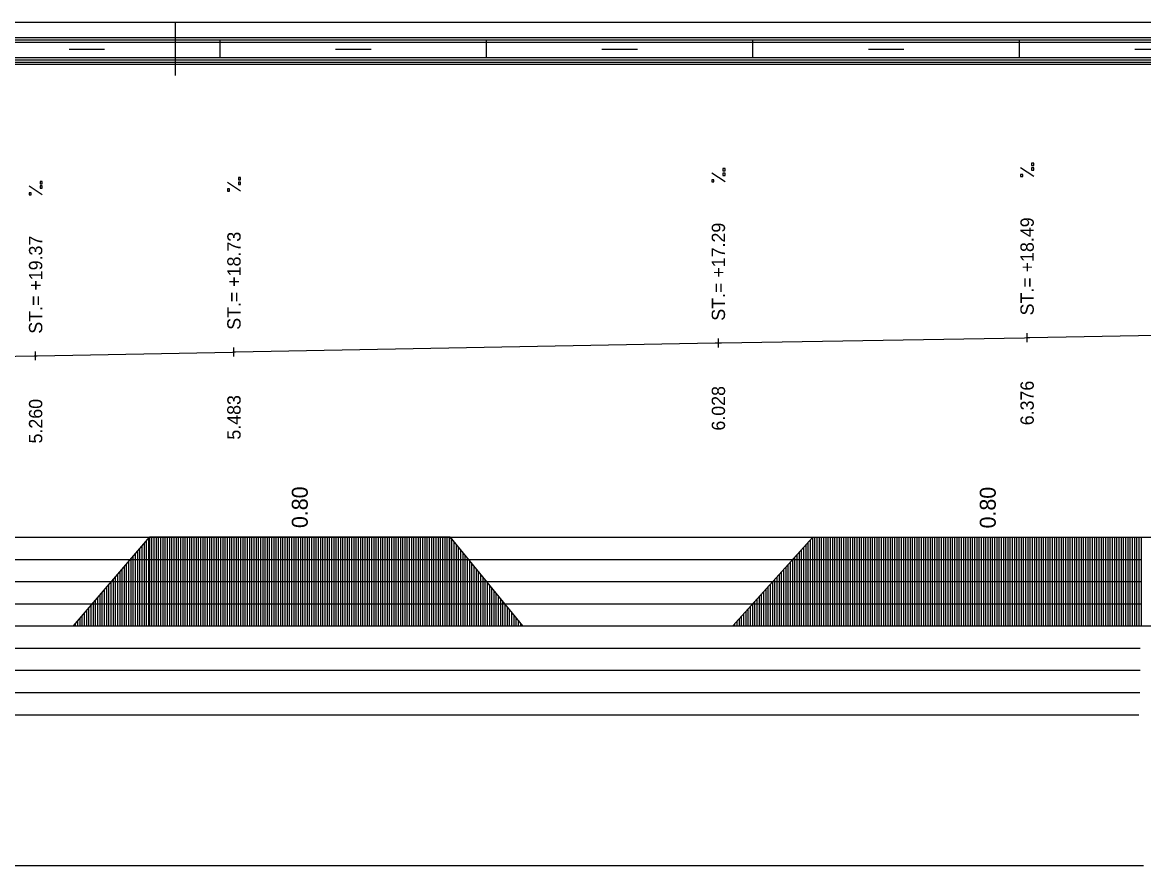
# Model space of a CAD drawing. Extents: x 2 to 10148, y 0 to 380.
# Drawn here: x 822.8 to 949, y 285 to 380 of the extents above; entities that cross this region are included whole.
import ezdxf

# ---------------------------------------------------------------- set-up
doc = ezdxf.new("R2010")
doc.units = 0
for name, color, linetype in [('NIVELETA_CARA', 7, 'Continuous'), ('NIVELETA_TEXT', 7, 'Continuous'), ('RAM', 7, 'Continuous'), ('ZRYCHL_CARA_C', 7, 'Continuous'), ('ZRYCHL_RASTR', 7, 'Continuous'), ('ZRYCHL_TEXT', 7, 'Continuous')]:
    doc.layers.add(name, color=color, linetype=linetype)

msp = doc.modelspace()

# ---------------------------------------------------------------- linework, layer by layer
at = {"layer": 'NIVELETA_CARA'}
for p, q in [((935.87, 343.99), (935.87, 344.99)), ((936.17, 344.49), (950.42, 344.76)), ((846.57, 342.37), (846.57, 343.37)), ((846.73, 342.87), (900.75, 343.88)), ((900.75, 343.88), (901.11, 343.89)), ((901.11, 343.39), (901.11, 344.39)), ((901.11, 343.89), (901.47, 343.89)), ((901.47, 343.89), (935.57, 344.48)), ((935.57, 344.48), (935.87, 344.49)), ((935.87, 344.49), (936.17, 344.49)), ((798.54, 341.95), (824.06, 342.43)), ((824.06, 342.43), (824.24, 342.43)), ((824.24, 341.93), (824.24, 342.93)), ((824.24, 342.43), (824.42, 342.44)), ((824.42, 342.44), (846.41, 342.86)), ((846.41, 342.86), (846.57, 342.87)), ((846.57, 342.87), (846.73, 342.87))]:
    msp.add_line(p, q, dxfattribs=at)
at = {"layer": 'NIVELETA_TEXT'}
for p, q in [((936.62, 362.62), (935.12, 363.61)), ((936.62, 364.13), (936.37, 364.13)), ((936.37, 364.13), (936.37, 363.89)), ((936.37, 363.89), (936.38, 363.88)), ((936.37, 363.88), (936.62, 363.88)), ((936.62, 363.62), (936.37, 363.62)), ((936.37, 363.62), (936.37, 363.38)), ((936.62, 363.88), (936.62, 364.13)), ((936.62, 363.37), (936.62, 363.62)), ((847.32, 362.51), (847.07, 362.51)), ((847.07, 362.51), (847.07, 362.27)), ((847.32, 362.26), (847.32, 362.51)), ((901.86, 362.02), (900.37, 363.01)), ((901.86, 363.53), (901.61, 363.53)), ((901.61, 363.53), (901.61, 363.29)), ((901.61, 363.29), (901.62, 363.28)), ((901.61, 363.28), (901.86, 363.28)), ((901.86, 363.02), (901.61, 363.02)), ((901.61, 363.02), (901.61, 362.78)), ((901.61, 362.78), (901.62, 362.77)), ((901.61, 362.77), (901.86, 362.77)), ((901.86, 363.28), (901.86, 363.53)), ((901.86, 362.77), (901.86, 363.02)), ((935.37, 362.86), (935.12, 362.86)), ((935.12, 362.86), (935.12, 362.62)), ((935.12, 362.62), (935.37, 362.62)), ((935.12, 362.62), (935.13, 362.62)), ((935.37, 362.62), (935.37, 362.86)), ((936.37, 363.38), (936.38, 363.37)), ((936.37, 363.37), (936.62, 363.37)), ((824.99, 360.56), (823.5, 361.55)), ((824.99, 362.08), (824.74, 362.08)), ((824.74, 362.08), (824.74, 361.83)), ((824.74, 361.83), (824.99, 361.83)), ((824.74, 361.83), (824.75, 361.83)), ((824.99, 361.57), (824.74, 361.57)), ((824.74, 361.57), (824.74, 361.32)), ((824.74, 361.32), (824.99, 361.32)), ((824.74, 361.32), (824.75, 361.32)), ((824.99, 361.83), (824.99, 362.08)), ((824.99, 361.32), (824.99, 361.57)), ((847.32, 360.99), (845.83, 361.98)), ((846.07, 361.24), (845.83, 361.24)), ((845.83, 361.24), (845.83, 361)), ((846.07, 360.99), (846.07, 361.24)), ((847.07, 362.27), (847.08, 362.26)), ((847.07, 362.26), (847.32, 362.26)), ((847.32, 362), (847.07, 362)), ((847.07, 362), (847.07, 361.76)), ((847.07, 361.76), (847.08, 361.75)), ((847.07, 361.75), (847.32, 361.75)), ((847.32, 361.75), (847.32, 362)), ((900.61, 362.26), (900.37, 362.26)), ((900.37, 362.26), (900.37, 362.02)), ((900.37, 362.02), (900.61, 362.02)), ((900.37, 362.02), (900.37, 362.02)), ((900.61, 362.02), (900.61, 362.26)), ((823.74, 360.81), (823.5, 360.81)), ((823.5, 360.81), (823.5, 360.57)), ((823.5, 360.57), (823.5, 360.56)), ((823.5, 360.56), (823.74, 360.56)), ((823.74, 360.56), (823.74, 360.81)), ((845.83, 361), (845.83, 360.99)), ((845.83, 360.99), (846.07, 360.99))]:
    msp.add_line(p, q, dxfattribs=at)
at = {"layer": 'RAM'}
for p, q in [((1245.39, 380), (631.22, 380)), ((840, 374), (840, 380)), ((1245.39, 378.25), (631.22, 378.25)), ((1245.39, 378), (631.22, 378)), ((1245.39, 377.75), (631.22, 377.75)), ((845, 376), (845, 378)), ((875, 376), (875, 378)), ((905, 376), (905, 378)), ((935, 376), (935, 378)), ((828, 377), (832, 377)), ((858, 377), (862, 377)), ((888, 377), (892, 377)), ((918, 377), (922, 377)), ((948, 377), (952, 377)), ((1245.39, 376), (631.22, 376)), ((1245.39, 375.75), (631.22, 375.75)), ((1245.39, 375.5), (631.22, 375.5)), ((1245.39, 375.25), (631.22, 375.25))]:
    msp.add_line(p, q, dxfattribs=at)
at = {"layer": 'ZRYCHL_CARA_C'}
for p, q in [((828.49, 312), (837.09, 322.03)), ((836.99, 312), (836.99, 321.92)), ((837.09, 312), (837.09, 322.03)), ((837.09, 322.03), (870.86, 322.03)), ((837.34, 312), (837.34, 322.03)), ((837.59, 312), (837.59, 322.03)), ((837.84, 312), (837.84, 322.03)), ((838.09, 312), (838.09, 322.03)), ((838.34, 312), (838.34, 322.03)), ((838.59, 312), (838.59, 322.03)), ((838.84, 312), (838.84, 322.03)), ((839.09, 312), (839.09, 322.03)), ((839.34, 312), (839.34, 322.03)), ((839.59, 312), (839.59, 322.03)), ((839.84, 312), (839.84, 322.03)), ((840.09, 312), (840.09, 322.03)), ((840.34, 312), (840.34, 322.03)), ((840.59, 312), (840.59, 322.03)), ((840.84, 312), (840.84, 322.03)), ((841.09, 312), (841.09, 322.03)), ((841.34, 312), (841.34, 322.03)), ((841.59, 312), (841.59, 322.03)), ((841.84, 312), (841.84, 322.03)), ((842.09, 312), (842.09, 322.03)), ((842.34, 312), (842.34, 322.03)), ((842.59, 312), (842.59, 322.03)), ((842.84, 312), (842.84, 322.03)), ((843.09, 312), (843.09, 322.03)), ((843.34, 312), (843.34, 322.03)), ((843.59, 312), (843.59, 322.03)), ((843.84, 312), (843.84, 322.03)), ((844.09, 312), (844.09, 322.03)), ((844.34, 312), (844.34, 322.03)), ((844.59, 312), (844.59, 322.03)), ((844.84, 312), (844.84, 322.03)), ((845.09, 312), (845.09, 322.03)), ((845.34, 312), (845.34, 322.03)), ((845.59, 312), (845.59, 322.03)), ((845.84, 312), (845.84, 322.03)), ((846.09, 312), (846.09, 322.03)), ((846.34, 312), (846.34, 322.03)), ((846.59, 312), (846.59, 322.03)), ((846.84, 312), (846.84, 322.03)), ((847.09, 312), (847.09, 322.03)), ((847.34, 312), (847.34, 322.03)), ((847.59, 312), (847.59, 322.03)), ((847.84, 312), (847.84, 322.03)), ((848.09, 312), (848.09, 322.03)), ((848.34, 312), (848.34, 322.03)), ((848.59, 312), (848.59, 322.03)), ((848.84, 312), (848.84, 322.03)), ((849.09, 312), (849.09, 322.03)), ((849.34, 312), (849.34, 322.03)), ((849.59, 312), (849.59, 322.03)), ((849.84, 312), (849.84, 322.03)), ((850.09, 312), (850.09, 322.03)), ((850.34, 312), (850.34, 322.03)), ((850.59, 312), (850.59, 322.03)), ((850.84, 312), (850.84, 322.03)), ((851.09, 312), (851.09, 322.03)), ((851.34, 312), (851.34, 322.03)), ((851.59, 312), (851.59, 322.03)), ((851.84, 312), (851.84, 322.03)), ((852.09, 312), (852.09, 322.03)), ((852.34, 312), (852.34, 322.03)), ((852.59, 312), (852.59, 322.03)), ((852.84, 312), (852.84, 322.03)), ((853.09, 312), (853.09, 322.03)), ((853.34, 312), (853.34, 322.03)), ((853.59, 312), (853.59, 322.03)), ((853.84, 312), (853.84, 322.03)), ((854.09, 312), (854.09, 322.03)), ((854.34, 312), (854.34, 322.03)), ((854.59, 312), (854.59, 322.03)), ((854.84, 312), (854.84, 322.03)), ((855.09, 312), (855.09, 322.03)), ((855.34, 312), (855.34, 322.03)), ((855.59, 312), (855.59, 322.03)), ((855.84, 312), (855.84, 322.03)), ((856.09, 312), (856.09, 322.03)), ((856.34, 312), (856.34, 322.03)), ((856.59, 312), (856.59, 322.03)), ((856.84, 312), (856.84, 322.03)), ((857.09, 312), (857.09, 322.03)), ((857.34, 312), (857.34, 322.03)), ((857.59, 312), (857.59, 322.03)), ((857.84, 312), (857.84, 322.03)), ((858.09, 312), (858.09, 322.03)), ((858.34, 312), (858.34, 322.03)), ((858.59, 312), (858.59, 322.03)), ((858.84, 312), (858.84, 322.03)), ((859.09, 312), (859.09, 322.03)), ((859.34, 312), (859.34, 322.03)), ((859.59, 312), (859.59, 322.03)), ((859.84, 312), (859.84, 322.03)), ((860.09, 312), (860.09, 322.03)), ((860.34, 312), (860.34, 322.03)), ((860.59, 312), (860.59, 322.03)), ((860.84, 312), (860.84, 322.03)), ((861.09, 312), (861.09, 322.03)), ((861.34, 312), (861.34, 322.03)), ((861.59, 312), (861.59, 322.03)), ((861.84, 312), (861.84, 322.03)), ((862.09, 312), (862.09, 322.03)), ((862.34, 312), (862.34, 322.03)), ((862.59, 312), (862.59, 322.03)), ((862.84, 312), (862.84, 322.03)), ((863.09, 312), (863.09, 322.03)), ((863.34, 312), (863.34, 322.03)), ((863.59, 312), (863.59, 322.03)), ((863.84, 312), (863.84, 322.03)), ((864.09, 312), (864.09, 322.03)), ((864.34, 312), (864.34, 322.03)), ((864.59, 312), (864.59, 322.03)), ((864.84, 312), (864.84, 322.03)), ((865.09, 312), (865.09, 322.03)), ((865.34, 312), (865.34, 322.03)), ((865.59, 312), (865.59, 322.03)), ((865.84, 312), (865.84, 322.03)), ((866.09, 312), (866.09, 322.03)), ((866.34, 312), (866.34, 322.03)), ((866.59, 312), (866.59, 322.03)), ((866.84, 312), (866.84, 322.03)), ((867.09, 312), (867.09, 322.03)), ((867.34, 312), (867.34, 322.03)), ((867.59, 312), (867.59, 322.03)), ((867.84, 312), (867.84, 322.03)), ((868.09, 312), (868.09, 322.03)), ((868.34, 312), (868.34, 322.03)), ((868.59, 312), (868.59, 322.03)), ((868.84, 312), (868.84, 322.03)), ((869.09, 312), (869.09, 322.03)), ((869.34, 312), (869.34, 322.03)), ((869.59, 312), (869.59, 322.03)), ((869.84, 312), (869.84, 322.03)), ((870.09, 312), (870.09, 322.03)), ((870.34, 312), (870.34, 322.03)), ((870.59, 312), (870.59, 322.03)), ((870.84, 312), (870.84, 322.03)), ((870.86, 312), (870.86, 322.03)), ((870.86, 322.03), (879.06, 312)), ((902.73, 312), (911.73, 321.99)), ((911.73, 312), (911.73, 321.99)), ((911.73, 321.99), (951.15, 321.99)), ((911.98, 312), (911.98, 321.99)), ((912.23, 312), (912.23, 321.99)), ((912.48, 312), (912.48, 321.99)), ((912.73, 312), (912.73, 321.99)), ((912.98, 312), (912.98, 321.99)), ((913.23, 312), (913.23, 321.99)), ((913.48, 312), (913.48, 321.99)), ((913.73, 312), (913.73, 321.99)), ((913.98, 312), (913.98, 321.99)), ((914.23, 312), (914.23, 321.99)), ((914.48, 312), (914.48, 321.99)), ((914.73, 312), (914.73, 321.99)), ((914.98, 312), (914.98, 321.99)), ((915.23, 312), (915.23, 321.99)), ((915.48, 312), (915.48, 321.99)), ((915.73, 312), (915.73, 321.99)), ((915.98, 312), (915.98, 321.99)), ((916.23, 312), (916.23, 321.99)), ((916.48, 312), (916.48, 321.99)), ((916.73, 312), (916.73, 321.99)), ((916.98, 312), (916.98, 321.99)), ((917.23, 312), (917.23, 321.99)), ((917.48, 312), (917.48, 321.99)), ((917.73, 312), (917.73, 321.99)), ((917.98, 312), (917.98, 321.99)), ((918.23, 312), (918.23, 321.99)), ((918.48, 312), (918.48, 321.99)), ((918.73, 312), (918.73, 321.99)), ((918.98, 312), (918.98, 321.99)), ((919.23, 312), (919.23, 321.99)), ((919.48, 312), (919.48, 321.99)), ((919.73, 312), (919.73, 321.99)), ((919.98, 312), (919.98, 321.99)), ((920.23, 312), (920.23, 321.99)), ((920.48, 312), (920.48, 321.99)), ((920.73, 312), (920.73, 321.99)), ((920.98, 312), (920.98, 321.99)), ((921.23, 312), (921.23, 321.99)), ((921.48, 312), (921.48, 321.99)), ((921.73, 312), (921.73, 321.99)), ((921.98, 312), (921.98, 321.99)), ((922.23, 312), (922.23, 321.99)), ((922.48, 312), (922.48, 321.99)), ((922.73, 312), (922.73, 321.99)), ((922.98, 312), (922.98, 321.99)), ((923.23, 312), (923.23, 321.99)), ((923.48, 312), (923.48, 321.99)), ((923.73, 312), (923.73, 321.99)), ((923.98, 312), (923.98, 321.99)), ((924.23, 312), (924.23, 321.99)), ((924.48, 312), (924.48, 321.99)), ((924.73, 312), (924.73, 321.99)), ((924.98, 312), (924.98, 321.99)), ((925.23, 312), (925.23, 321.99)), ((925.48, 312), (925.48, 321.99)), ((925.73, 312), (925.73, 321.99)), ((925.98, 312), (925.98, 321.99)), ((926.23, 312), (926.23, 321.99)), ((926.48, 312), (926.48, 321.99)), ((926.73, 312), (926.73, 321.99)), ((926.98, 312), (926.98, 321.99)), ((927.23, 312), (927.23, 321.99)), ((927.48, 312), (927.48, 321.99)), ((927.73, 312), (927.73, 321.99)), ((927.98, 312), (927.98, 321.99)), ((928.23, 312), (928.23, 321.99)), ((928.48, 312), (928.48, 321.99)), ((928.73, 312), (928.73, 321.99)), ((928.98, 312), (928.98, 321.99)), ((929.23, 312), (929.23, 321.99)), ((929.48, 312), (929.48, 321.99)), ((929.73, 312), (929.73, 321.99)), ((929.98, 312), (929.98, 321.99)), ((930.23, 312), (930.23, 321.99)), ((930.48, 312), (930.48, 321.99)), ((930.73, 312), (930.73, 321.99)), ((930.98, 312), (930.98, 321.99)), ((931.23, 312), (931.23, 321.99)), ((931.48, 312), (931.48, 321.99)), ((931.73, 312), (931.73, 321.99)), ((931.98, 312), (931.98, 321.99)), ((932.23, 312), (932.23, 321.99)), ((932.48, 312), (932.48, 321.99)), ((932.73, 312), (932.73, 321.99)), ((932.98, 312), (932.98, 321.99)), ((933.23, 312), (933.23, 321.99)), ((933.48, 312), (933.48, 321.99)), ((933.73, 312), (933.73, 321.99)), ((933.98, 312), (933.98, 321.99)), ((934.23, 312), (934.23, 321.99)), ((934.48, 312), (934.48, 321.99)), ((934.73, 312), (934.73, 321.99)), ((934.98, 312), (934.98, 321.99)), ((935.23, 312), (935.23, 321.99)), ((935.48, 312), (935.48, 321.99)), ((935.73, 312), (935.73, 321.99)), ((935.98, 312), (935.98, 321.99)), ((936.23, 312), (936.23, 321.99)), ((936.48, 312), (936.48, 321.99)), ((936.73, 312), (936.73, 321.99)), ((936.98, 312), (936.98, 321.99)), ((937.23, 312), (937.23, 321.99)), ((937.48, 312), (937.48, 321.99)), ((937.73, 312), (937.73, 321.99)), ((937.98, 312), (937.98, 321.99)), ((938.23, 312), (938.23, 321.99)), ((938.48, 312), (938.48, 321.99)), ((938.73, 312), (938.73, 321.99)), ((938.98, 312), (938.98, 321.99)), ((939.23, 312), (939.23, 321.99)), ((939.48, 312), (939.48, 321.99)), ((939.73, 312), (939.73, 321.99)), ((939.98, 312), (939.98, 321.99)), ((940.23, 312), (940.23, 321.99)), ((940.48, 312), (940.48, 321.99)), ((940.73, 312), (940.73, 321.99)), ((940.98, 312), (940.98, 321.99)), ((941.23, 312), (941.23, 321.99)), ((941.48, 312), (941.48, 321.99)), ((941.73, 312), (941.73, 321.99)), ((941.98, 312), (941.98, 321.99)), ((942.23, 312), (942.23, 321.99)), ((942.48, 312), (942.48, 321.99)), ((942.73, 312), (942.73, 321.99)), ((942.98, 312), (942.98, 321.99)), ((943.23, 312), (943.23, 321.99)), ((943.48, 312), (943.48, 321.99)), ((943.73, 312), (943.73, 321.99)), ((943.98, 312), (943.98, 321.99)), ((944.23, 312), (944.23, 321.99)), ((944.48, 312), (944.48, 321.99)), ((944.73, 312), (944.73, 321.99)), ((944.98, 312), (944.98, 321.99)), ((945.23, 312), (945.23, 321.99)), ((945.48, 312), (945.48, 321.99)), ((945.73, 312), (945.73, 321.99)), ((945.98, 312), (945.98, 321.99)), ((946.23, 312), (946.23, 321.99)), ((946.48, 312), (946.48, 321.99)), ((946.73, 312), (946.73, 321.99)), ((946.98, 312), (946.98, 321.99)), ((947.23, 312), (947.23, 321.99)), ((947.48, 312), (947.48, 321.99)), ((947.73, 312), (947.73, 321.99)), ((947.98, 312), (947.98, 321.99)), ((948.23, 312), (948.23, 321.99)), ((948.48, 312), (948.48, 321.99)), ((948.73, 312), (948.73, 321.99)), ((835.99, 312), (835.99, 320.75)), ((836.24, 312), (836.24, 321.04)), ((836.49, 312), (836.49, 321.33)), ((836.74, 312), (836.74, 321.63)), ((871.11, 312), (871.11, 321.73)), ((871.36, 312), (871.36, 321.42)), ((871.61, 312), (871.61, 321.12)), ((871.86, 312), (871.86, 320.81)), ((910.73, 312), (910.73, 320.88)), ((910.98, 312), (910.98, 321.16)), ((911.23, 312), (911.23, 321.44)), ((911.48, 312), (911.48, 321.72)), ((834.99, 312), (834.99, 319.58)), ((835.24, 312), (835.24, 319.88)), ((835.49, 312), (835.49, 320.17)), ((835.74, 312), (835.74, 320.46)), ((872.11, 312), (872.11, 320.5)), ((872.36, 312), (872.36, 320.2)), ((872.61, 312), (872.61, 319.89)), ((872.86, 312), (872.86, 319.59)), ((909.48, 312), (909.48, 319.5)), ((909.73, 312), (909.73, 319.77)), ((909.98, 312), (909.98, 320.05)), ((910.23, 312), (910.23, 320.33)), ((910.48, 312), (910.48, 320.61)), ((833.74, 312), (833.74, 318.13)), ((833.99, 312), (833.99, 318.42)), ((834.24, 312), (834.24, 318.71)), ((834.49, 312), (834.49, 319)), ((834.74, 312), (834.74, 319.29)), ((873.11, 312), (873.11, 319.28)), ((873.36, 312), (873.36, 318.97)), ((873.61, 312), (873.61, 318.67)), ((873.86, 312), (873.86, 318.36)), ((908.23, 312), (908.23, 318.11)), ((908.48, 312), (908.48, 318.39)), ((908.73, 312), (908.73, 318.66)), ((908.98, 312), (908.98, 318.94)), ((909.23, 312), (909.23, 319.22)), ((832.74, 312), (832.74, 316.96)), ((832.99, 312), (832.99, 317.25)), ((833.24, 312), (833.24, 317.54)), ((833.49, 312), (833.49, 317.83)), ((874.11, 312), (874.11, 318.06)), ((874.36, 312), (874.36, 317.75)), ((874.61, 312), (874.61, 317.45)), ((874.86, 312), (874.86, 317.14)), ((875.11, 312), (875.11, 316.83)), ((907.23, 312), (907.23, 317)), ((907.48, 312), (907.48, 317.27)), ((907.73, 312), (907.73, 317.55)), ((907.98, 312), (907.98, 317.83)), ((831.74, 312), (831.74, 315.79)), ((831.99, 312), (831.99, 316.08)), ((832.24, 312), (832.24, 316.38)), ((832.49, 312), (832.49, 316.67)), ((875.36, 312), (875.36, 316.53)), ((875.61, 312), (875.61, 316.22)), ((875.86, 312), (875.86, 315.92)), ((876.11, 312), (876.11, 315.61)), ((905.98, 312), (905.98, 315.61)), ((906.23, 312), (906.23, 315.89)), ((906.48, 312), (906.48, 316.16)), ((906.73, 312), (906.73, 316.44)), ((906.98, 312), (906.98, 316.72)), ((830.49, 312), (830.49, 314.33)), ((830.74, 312), (830.74, 314.63)), ((830.99, 312), (830.99, 314.92)), ((831.24, 312), (831.24, 315.21)), ((831.49, 312), (831.49, 315.5)), ((876.36, 312), (876.36, 315.3)), ((876.61, 312), (876.61, 315)), ((876.86, 312), (876.86, 314.69)), ((877.11, 312), (877.11, 314.39)), ((904.98, 312), (904.98, 314.5)), ((905.23, 312), (905.23, 314.78)), ((905.48, 312), (905.48, 315.05)), ((905.73, 312), (905.73, 315.33)), ((829.49, 312), (829.49, 313.17)), ((829.74, 312), (829.74, 313.46)), ((829.99, 312), (829.99, 313.75)), ((830.24, 312), (830.24, 314.04)), ((877.36, 312), (877.36, 314.08)), ((877.61, 312), (877.61, 313.77)), ((877.86, 312), (877.86, 313.47)), ((878.11, 312), (878.11, 313.16)), ((903.73, 312), (903.73, 313.11)), ((903.98, 312), (903.98, 313.39)), ((904.23, 312), (904.23, 313.67)), ((904.48, 312), (904.48, 313.94)), ((904.73, 312), (904.73, 314.22)), ((631.22, 312), (1245.39, 312)), ((828.74, 312), (828.74, 312.29)), ((828.99, 312), (828.99, 312.58)), ((829.24, 312), (829.24, 312.88)), ((878.36, 312), (878.36, 312.86)), ((878.61, 312), (878.61, 312.55)), ((878.86, 312), (878.86, 312.24)), ((902.98, 312), (902.98, 312.28)), ((903.23, 312), (903.23, 312.56)), ((903.48, 312), (903.48, 312.83))]:
    msp.add_line(p, q, dxfattribs=at)
at = {"layer": 'ZRYCHL_RASTR'}
for p, q in [((742, 322), (948.7, 322)), ((742, 319.5), (948.73, 319.5)), ((742, 317), (948.69, 317)), ((742, 314.5), (948.68, 314.5)), ((742, 309.5), (948.61, 309.5)), ((742, 307), (948.58, 307)), ((742, 304.5), (948.56, 304.5)), ((742, 302), (948.46, 302)), ((742, 285), (948.98, 285))]:
    msp.add_line(p, q, dxfattribs=at)

# ---------------------------------------------------------------- texts
at = {"layer": 'NIVELETA_TEXT'}
for s, p in [('ST.= +17.29', (901.86, 346.39)), ('ST.= +18.49', (936.62, 346.99)), ('ST.= +18.73', (847.32, 345.37)), ('ST.= +19.37', (824.99, 344.93)), ('6.028', (901.86, 334.01)), ('6.376', (936.62, 334.61)), ('5.260', (824.99, 332.56)), ('5.483', (847.32, 332.99))]:
    msp.add_text(s, height=1.5, rotation=90, dxfattribs=at).set_placement(p)
at = {"layer": 'ZRYCHL_TEXT'}
for p in [(854.88, 323.03), (932.34, 322.99)]:
    msp.add_text('0.80', height=1.8, rotation=90, dxfattribs=at).set_placement(p)

doc.saveas('drawing.dxf')
